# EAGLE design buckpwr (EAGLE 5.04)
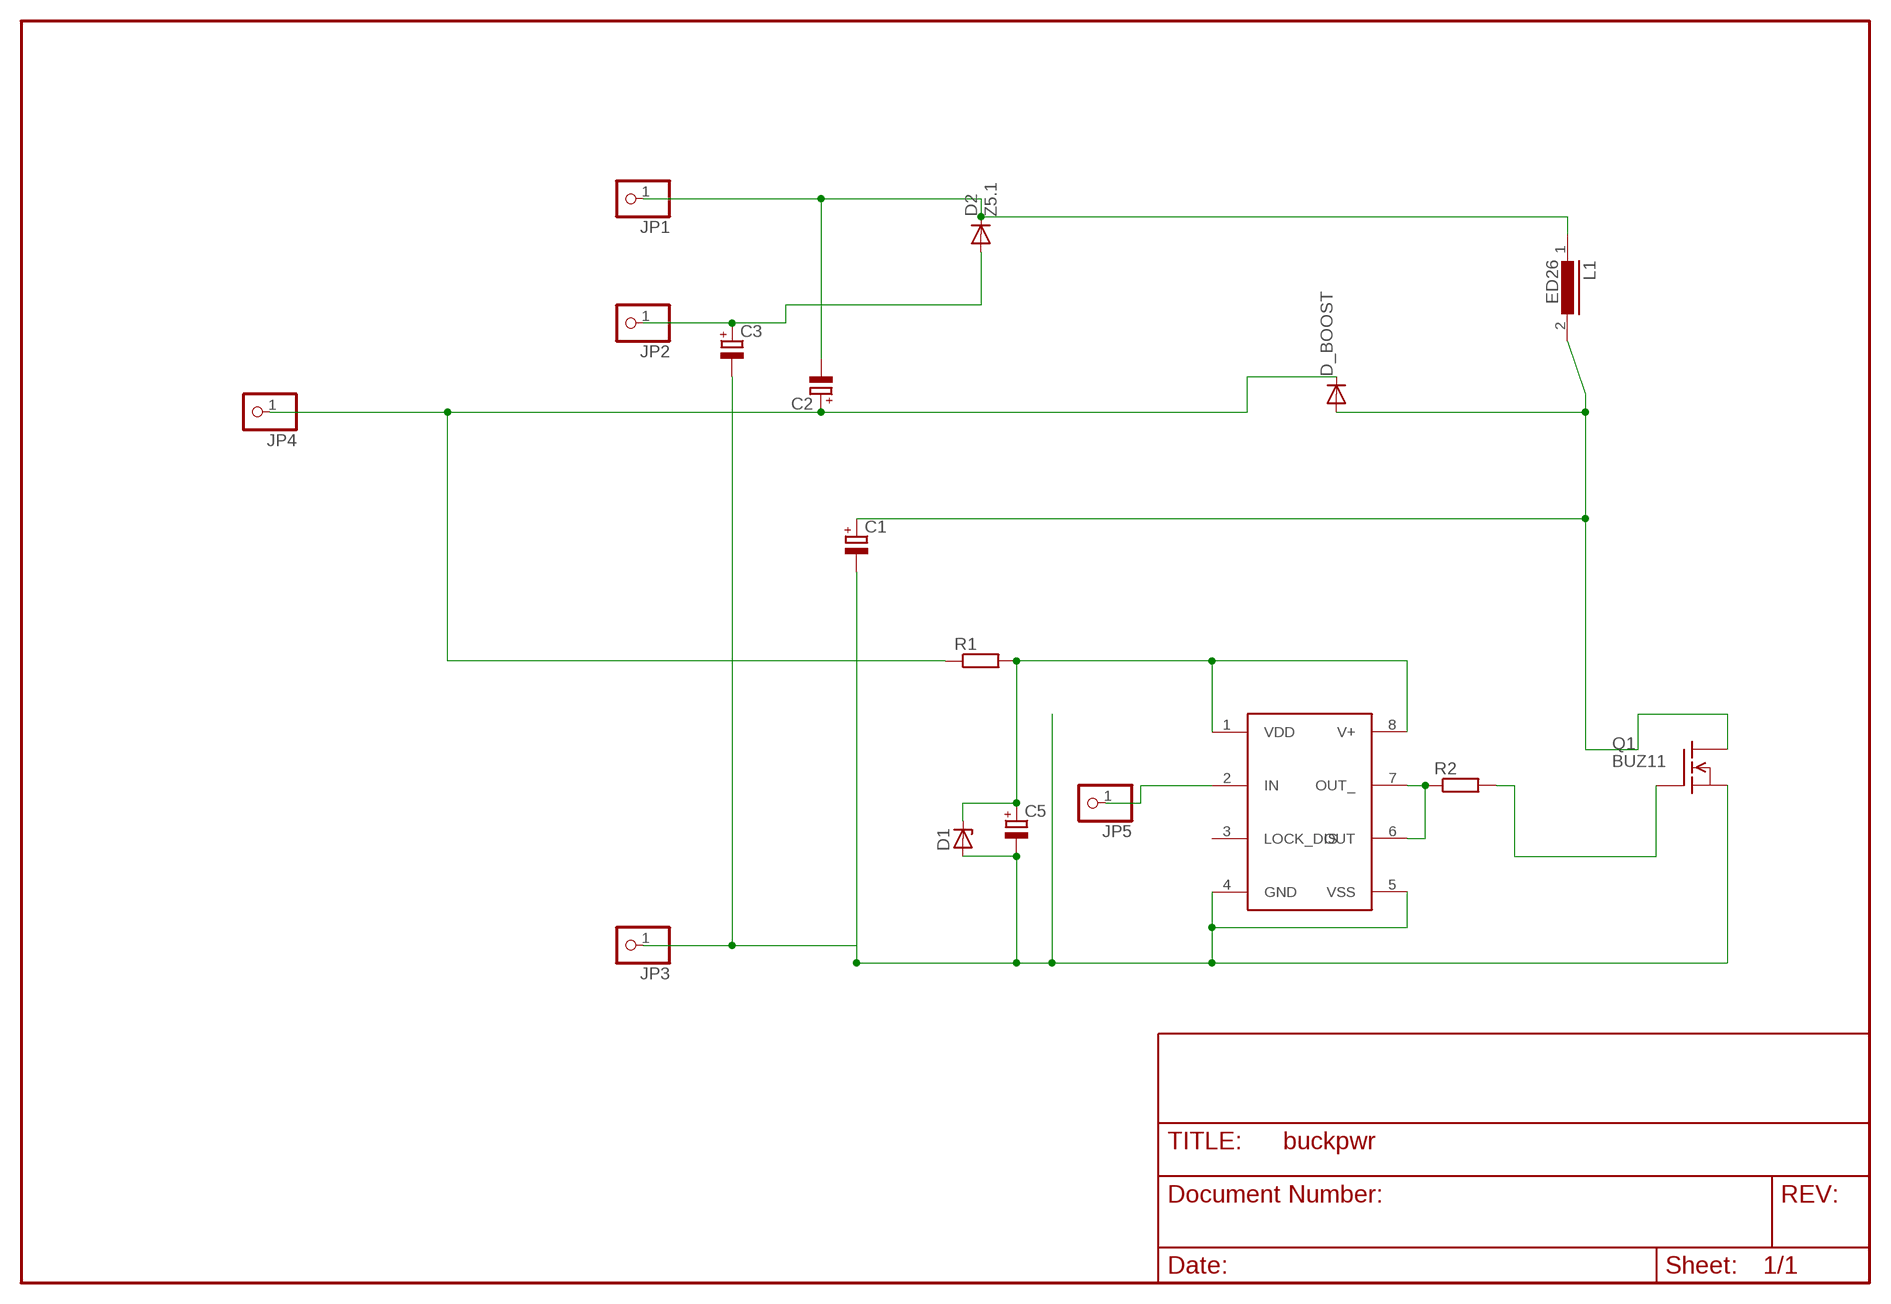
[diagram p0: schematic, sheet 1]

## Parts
C1  CPOL-EUE2.5-7  [E2,5-7]
C2  CPOL-EUE5-10.5  [E5-10,5]
C3  CPOL-EUE2-4  [E2-4]
C5  CPOL-EUE2-4  [E2-4]
D1  ZENER-DIODEZD-2.5  [ZDIO-2.5]
D2  Z5.1  DIODE-D-2.5  [D-2.5]
D_BOOST  DIODE-D-10  [D-10]
IC1  TC4432X  [SO-08]
JP1  PINHD-1X1  [1X01]
JP2  PINHD-1X1  [1X01]
JP3  PINHD-1X1  [1X01]
JP4  PINHD-1X1  [1X01]
JP5  PINHD-1X1  [1X01]
L1  ED26  [ED26]
Q1  BUZ11  [TO220V]
R1  R-EU_0207/15  [0207/15]
R2  R-EU_R1206  [R1206]

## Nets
GND: C1.- C3.- C5.- D1.A IC1.4(GND) IC1.5(VSS) JP3.1 Q1.3(S)
HOTSPOT: C1.+ D_BOOST.A L1.2 Q1.2(D)
N$1: IC1.2(IN) JP5.1
N$2: C2.- D2.C JP1.1 L1.1
N$3: IC1.6(OUT) IC1.7(OUT_) R2.1
N$4: C3.+ D2.A JP2.1
N$5: C2.+ D_BOOST.C JP4.1 R1.1
N$6: Q1.1(G) R2.2
N$7: C5.+ D1.C IC1.1(VDD) IC1.8(V+) R1.2
Unconnected: IC1.3(LOCK_DIS)

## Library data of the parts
C1-C3 C5 = rcl(2):CPOL-EU: POLARIZED CAPACITOR, European symbol
D1 = diode-1:ZENER-DIODE: Z-Diode
D2 D_BOOST = diode:DIODE-: DIODE
IC1 = microchip:TC4432
JP1-JP5 = pinhead:PINHD-1X1: PIN HEADER
L1 = inductors:ED26: INDUCTOR
Q1 = transistor-fet:BUZ11: N-Channel Enhancement MOSFET 50V; 30A; 0,040Ohm
R1 R2 = rcl-2:R-EU_: RESISTOR, European symbol

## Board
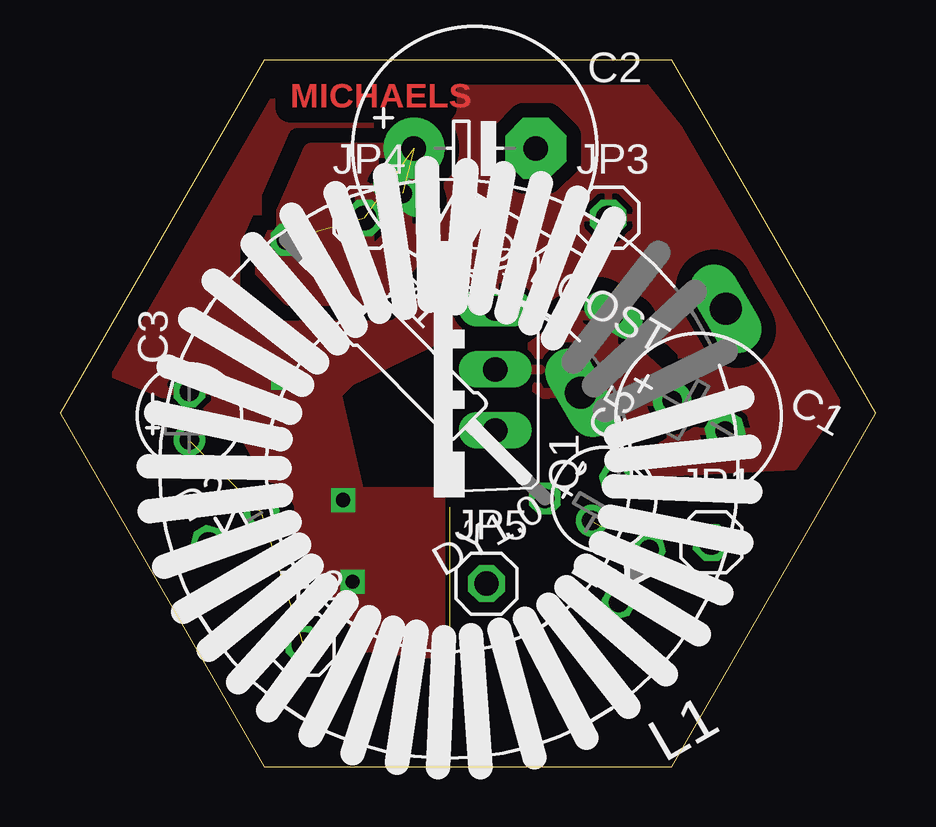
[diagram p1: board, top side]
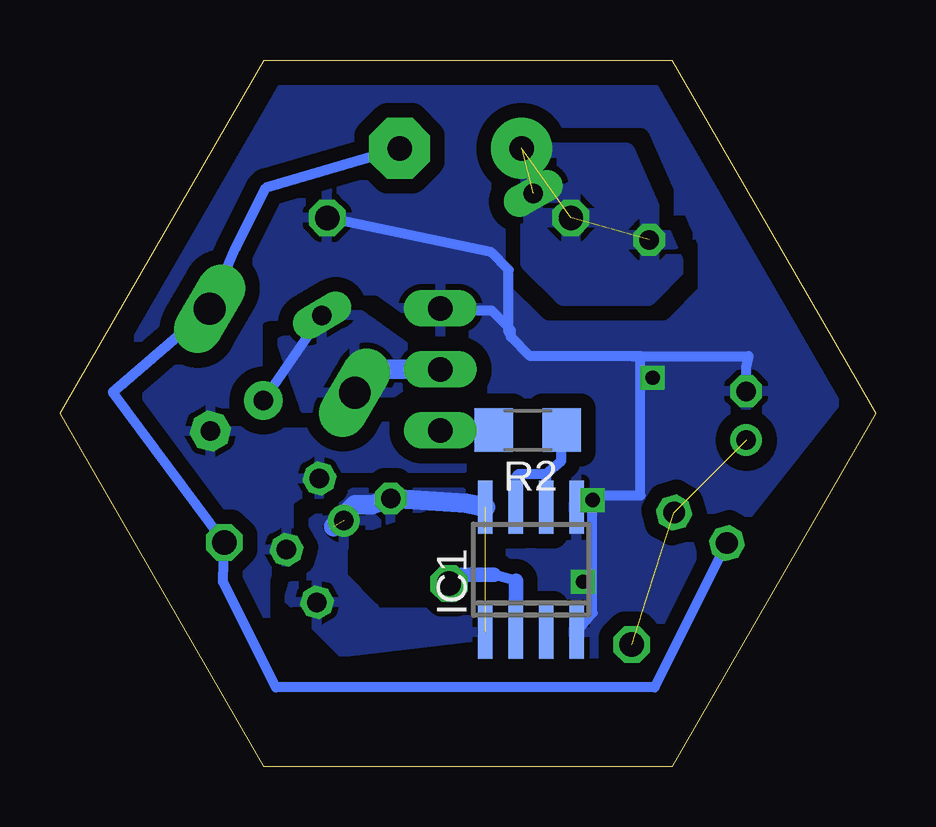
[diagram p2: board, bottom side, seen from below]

Size 34 x 29.44 mm. Coordinates in mm from the lower left corner, seen from the top.
Outline: 8.5,0 25.5,0 34,14.72 25.5,29.44 8.5,29.44 0,14.72 8.5,0
Copper layers (1*16): Top 0.035mm / dielectric 1.5mm / Bottom 0.035mm
Design rules "default": minimum track width 10mil, minimum drill 24mil, track to track 8mil, track to pad 8mil, pad to pad 8mil, via to via 8mil, smd to smd 8mil, copper to edge 40mil, drill to drill 8mil, minimum pad ring 10mil, minimum via ring 8mil, stop-mask expansion 4mil, vias tented up to drill 0mil, thermal gap 10mil

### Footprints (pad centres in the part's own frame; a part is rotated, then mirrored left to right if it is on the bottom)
E2,5-7 = drill 0.813 pad 1.6 round: + -1.27,0 | drill 0.813 pad 1.6 octagon: - 1.27,0
E5-10,5 = drill 1.016 pad 2.54 round: + -2.54,0 | drill 1.016 pad 2.54 octagon: - 2.54,0
E2-4 = drill 0.813 pad 1.27 round: + -1.016,0 | drill 0.813 pad 1.27 octagon: - 1.016,0
ZDIO-2.5 = drill 0.813 octagon: A 1.27,0; C -1.27,0
D-2.5 = drill 0.9 octagon: A 1.27,0; C -1.27,0
D-10 = drill 0.813 long: A 5.08,0; C -5.08,0
SO-08 = smd 0.6 x 2.2: 1 -1.905,-2.6; 2 -0.635,-2.6; 3 0.635,-2.6; 4 1.905,-2.6; 5 1.905,2.6; 6 0.635,2.6; 7 -0.635,2.6; 8 -1.905,2.6
1X01 = drill 1.016 octagon: 1 0,0
ED26 = drill 1.321 long: 1 -13.335,0; 2 -6.35,0
TO220V = drill 1.016 long: 1 -2.54,-2.54; 2 0,-2.54; 3 2.54,-2.54
0207/15 = drill 0.813 octagon: 1 -7.62,0; 2 7.62,0
R1206 = smd 1.6 x 1.803: 1 -1.422,0; 2 1.422,0

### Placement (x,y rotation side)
C1  26.63,14.61 330 top
C2  17.3,25.75 0 top
C3  5.39,14.62 90 top
C5  22.67,11.12 60 top
D1  23.92,7.94 60 top
D2  7.3,9.95 30 top
D_BOOST  18.67,21.34 330 top
IC1  14.37,8.2 0 bottom
JP1  27.15,9.34 0 top
JP2  10.16,5.08 0 top
JP3  22.86,22.86 0 top
JP4  12.7,22.86 0 top
JP5  17.78,7.62 0 top
L1  16.21,12.4 210 top
Q1  15.6,16.55 90 top
R1  14.82,16.56 315 top
R2  14.5,14.02 180 bottom

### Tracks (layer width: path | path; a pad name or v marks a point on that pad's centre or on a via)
GND  (via drill 0.6)
  Bottom 0.406: IC1.4 11.8,6.4 v11.8,11.1 11.8,11.3 11.72,11.3 | 11.72,11.3 IC1.5 | 11.72,11.3 9.8,11.3 9.8,17.1 10.2,17.1 | 10.2,17.1 5.3,17.1 5.4,16.64 C3.- | 10.2,17.1 14.4,17.1 15.2,17.9 15.2,18 | 15.2,18 15.2,18.2 16,19 17.81,19 | JP3.1 16.02,21.42 15.3,20.7 15.3,18.1 15.2,18
  other vias: 12.2,7.7 9.3,16.2
  pour Bottom (isolate 0.61, rank 3): 0.9,16.1 8,29.7 26.5,29.9 32.7,16.2 24.8,4.8 9.9,4.7
  pour Top (isolate 0.61, rank 3): 23.8,29.1 33.6,16.9 30.6,12.5 24.7,12.2 24.7,18.4 17.5,18.6 12.1,16 11.6,15.5 12.5,11.5 15.9,11.5 15.9,4.6 12.8,4.9 7.4,14.2 1.1,16.8 8.7,29.2
HOTSPOT
  Bottom 0.406: D_BOOST.A C1.+
  Bottom 0.813: Q1.2 20.74,16.55 L1.2
  pour Bottom: 18.5,16.7 21.6,18.9 24.8,17.7 23.8,14.9 20.1,15.6
  pour Top: 18.5,16.7 21.6,18.9 23.7,17.6 26.1,15.4 23,13.5
N$1
  Bottom 0.406: 15,7.74 15.9,8
  Bottom 0.61: IC1.2 15,7.74 | 15.9,8 17.25,8 JP5.1
N$2
  Bottom 0.406: C2.- 25.4,24.13 26.67,21.61 L1.1 31.8,15.6 JP1.1 27.2,7.7 25,3.3 9.2,3.3 D2.C
N$3
  Bottom 0.406: 13.73,12.2 IC1.6 | 13.73,12.2 13.1,12.73 R2.1 | IC1.7 15,12.06 14.87,12.2 13.73,12.2
N$4  (2 unrouted)
N$5  (3 unrouted)
  pour Bottom (isolate 0.305): 10.4,25.6 14.2,25.6 14.4,25.4 14.4,21 13,19.6 9.5,19.6 8.3,20.8
  pour Top (isolate 0.305): 10.5,25.6 14.3,25.6 14.5,25.4 14.5,21 13.1,19.6 9.6,19.6 8.4,20.8
N$6
  Bottom 0.813: Q1.1 15.93,14.01 R2.2
N$7  (2 unrouted)
  Bottom 0.813: 22.6,10 21.7,10.9 20.98,10.9 R1.2 17.07,10.97 IC1.8
  pour Bottom (isolate 0.61): 17.2,11.4 21.8,11.4 23.5,10.2 24.47,6.96 22.27,4.76 16.8,5.4 16.8,5.9 17.3,6.4 20.8,6.4 20.9,6.5 20.9,6.6 22.2,7.9 22.2,9.1 21.4,9.9

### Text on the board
Top: MICHAELS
